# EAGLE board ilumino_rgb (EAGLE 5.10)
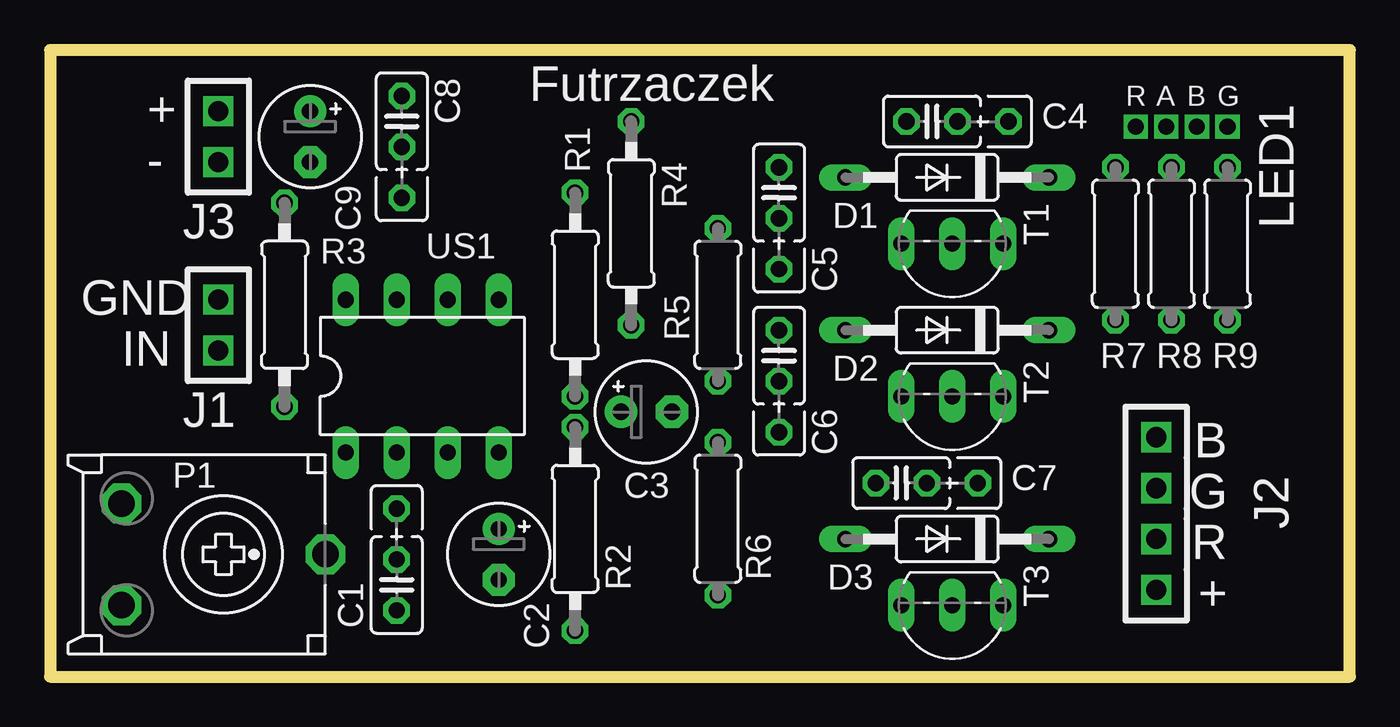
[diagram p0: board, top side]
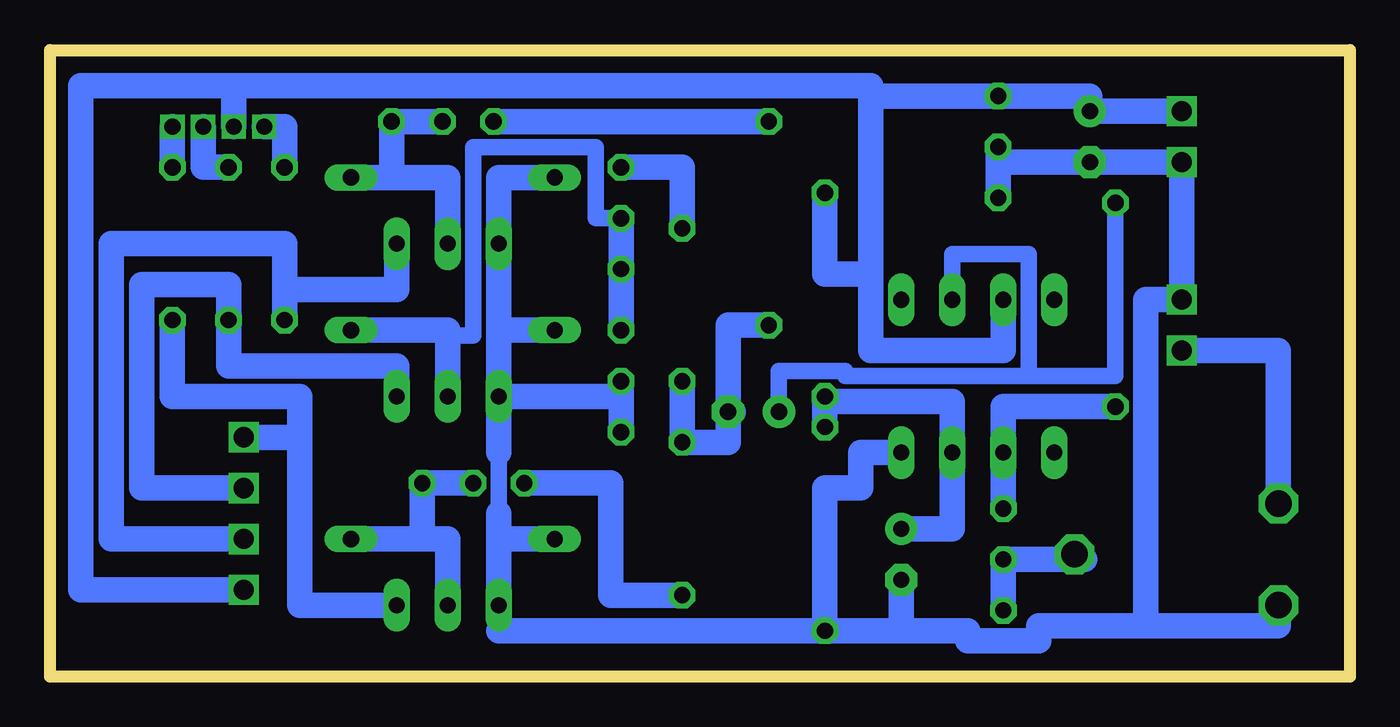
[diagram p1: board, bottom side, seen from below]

Size 64.77 x 31.24 mm. Coordinates in mm from the lower left corner, seen from the top.
Outline: 0,0 64.77,0 64.77,31.24 0,31.24 0,0
Copper layers (1*16): Top 0.035mm / dielectric 1.5mm / Bottom 0.035mm
Design rules "default": minimum track width 10mil, minimum drill 24mil, track to track 8mil, track to pad 8mil, pad to pad 8mil, via to via 8mil, smd to smd 8mil, copper to edge 40mil, drill to drill 8mil, minimum pad ring 10mil, minimum via ring 8mil, stop-mask expansion 4mil, vias tented up to drill 0mil, thermal gap 10mil

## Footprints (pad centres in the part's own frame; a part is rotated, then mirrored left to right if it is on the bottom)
C025_050-025X075 = drill 0.813 octagon: 1 -1.27,0; 2 1.27,0; 3 3.81,0
E2,5-5 = drill 0.813 pad 1.6 round: + -1.27,0 | drill 0.813 pad 1.6 octagon: - 1.27,0
C2992 = drill 0.813 long: A 5.08,0; C -5.08,0
ECP10S = drill 1.321 octagon: A -2.54,-5.08; E 2.54,-5.08; S 0,5.08
0207/10 = drill 0.813 octagon: 1 -5.08,0; 2 5.08,0
0207/7 = drill 0.813 octagon: 1 -3.81,0; 2 3.81,0
TO92- = drill 0.813 long: 1 2.54,0; 2 0,0; 3 -2.54,0
DIL08 = drill 0.813 long: 1 -3.81,-3.81; 2 -1.27,-3.81; 3 1.27,-3.81; 4 3.81,-3.81; 5 3.81,3.81; 6 1.27,3.81; 7 -1.27,3.81; 8 -3.81,3.81

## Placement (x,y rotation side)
C1  [C025_050-025X075]  17.27,4.57 90 top
C2  [E2,5-5]  22.35,6.1 270 top
C3  [E2,5-5]  29.72,13.21 0 top
C4  [C025_050-025X075]  43.94,27.69 0 top
C5  [C025_050-025X075]  36.32,24.13 270 top
C6  [C025_050-025X075]  36.32,16 270 top
C7  [C025_050-025X075]  42.42,9.65 0 top
C8  [C025_050-025X075]  17.53,27.69 270 top
C9  [E2,5-5]  12.95,26.92 270 top
D1  [C2992]  44.7,24.89 180 top
D2  [C2992]  44.7,17.27 180 top
D3  [C2992]  44.7,6.86 180 top
P1  [ECP10S]  8.64,6.1 270 top
R1  [0207/10]  26.16,19.05 270 top
R2  [0207/10]  26.16,7.37 270 top
R3  [0207/10]  11.68,18.54 90 top
R4  [0207/10]  28.96,22.61 270 top
R5  [0207/7]  33.27,18.54 270 top
R6  [0207/7]  33.27,7.87 270 top
R7  [0207/7]  53.09,21.59 270 top
R8  [0207/7]  55.88,21.59 270 top
R9  [0207/7]  58.67,21.59 270 top
T1  [TO92-]  44.96,21.59 180 top
T2  [TO92-]  44.96,13.97 180 top
T3  [TO92-]  44.96,3.56 180 top
US1  [DIL08]  18.54,14.99 0 top

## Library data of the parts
C1-C9 R1-R9 = rcl
D1-D3 = diode
P1 = pot
T1-T3 = transistor-npn
US1 = 40xx

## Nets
S$1: C2.+ R1.2 R2.1 US1.3
S$2: C8.1 C9.+ R1.1 US1.7
S$4: C3.+
S$5: R3.2
S$6: C1.3 R3.1
S$7: C1.1 C1.2 P1.S
S$8: C8.2 C8.3 C9.-
S$9: P1.A
S$12: C3.- R4.2 R5.2 R6.1
S$13: C6.2 C6.3
S$14: C4.2 T1.2
S$15: C7.1 R6.2
S$16: C5.2 C6.1 T2.2
S$18: C7.2 T3.2
S$19: R5.1
S$20: C2.- P1.E R2.2 US1.4
S$21: R9.2 T3.3
S$27: C4.1 R4.1
S$28: R8.1
S$29: R9.1
S$30: R7.1
S$31: T1.3
S$32: R8.2 T2.3

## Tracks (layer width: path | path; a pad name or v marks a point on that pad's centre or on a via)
S$1
  Bottom 1.27: R2.1 R1.2 26.16,13.72 19.81,13.72 19.81,11.43 US1.3 19.81,7.37 C2.+
S$2  (via drill 0.8, 1)
  Bottom 1.27: 8.64,28.19 C9.+ 12.95,28.96 C8.1 23.88,28.96 23.88,28.7 | US1.7 17.27,16.26 23.88,16.26 23.88,18.8 | 23.88,18.8 23.88,20.07 26.16,20.07 R1.1 | 23.88,28.7 23.88,18.8 | 23.88,28.7 23.88,29.46 52.83,29.46 | 52.83,29.46 55.63,29.46 v55.63,27.43 | 52.83,29.46 63.25,29.46 63.25,4.32 v55.12,4.32
S$3  (via drill 1)
  other vias: 55.12,6.86
S$4
  Bottom 0.813: 19.81,18.29 19.81,21.08 16,21.08 16,14.99 25.15,14.99 25.15,15.24 28.45,15.24 C3.+
S$5
  Bottom 0.813: 16.26,14.99 11.68,14.99 R3.2
S$6
  Bottom 1.27: 17.27,10.67 17.27,11.18 | 17.27,11.18 17.27,13.46 R3.1 | C1.3 17.27,11.18
S$7
  Bottom 1.27: C1.1 C1.2 13.21,5.84 P1.S
S$8  (via drill 1)
  Bottom 1.27: 10.16,2.79 10.16,18.8 v8.38,18.8 v8.38,25.65 C9.- 17.53,25.65 | 17.53,25.65 C8.2 | 17.53,25.65 C8.3
S$9  (via drill 1)
  Bottom 1.27: v8.38,16.26 3.56,16.26 P1.A
S$10  (via drill 1)
  other vias: 8.38,28.19
S$12
  Bottom 1.27: C3.- 30.73,13.21 | R4.2 30.99,17.53 C3.- | C3.- 30.99,11.68 R6.1 R5.2
S$13
  Bottom 0.813: 42.42,11.18 42.42,7.87
  Bottom 1.27: 39.37,24.89 42.42,24.89 42.42,22.1 | 42.42,22.1 42.42,21.34 | 42.42,13.97 42.42,11.18 | 42.42,13.97 42.42,22.1 | 42.42,13.97 36.32,13.97 36.32,14.48 | 36.32,14.48 C6.2 | C6.3 36.32,14.48 | 39.37,6.86 42.42,6.86 42.42,6.6 | 42.42,6.6 42.42,7.87 42.42,8.13 | 42.42,3.3 42.42,6.6
S$14
  Bottom 1.27: 49.53,24.89 47.75,24.89 | 47.75,24.89 44.96,24.89 T1.2 | C4.2 47.75,27.69 47.75,24.89
S$15
  Bottom 1.27: R6.2 36.83,4.06 36.83,9.65 C7.1
S$16
  Bottom 0.813: 44.96,17.02 43.69,17.02 43.69,26.42 37.59,26.42 37.59,22.86 C5.2
  Bottom 1.27: 49.53,17.27 44.96,17.27 44.96,17.02 T2.2 | C5.2 C6.1
S$17
  Bottom 1.27: 39.37,17.27 42.42,17.27 42.42,13.72
S$18
  Bottom 1.27: 49.53,6.86 46.23,6.86 | 46.23,6.86 44.96,6.86 T3.2 | C7.2 46.23,9.65 46.23,6.86
S$19
  Bottom 1.27: 36.32,25.4 33.27,25.4 R5.1
S$20
  Bottom 1.27: US1.4 24.38,11.18 24.38,9.4 26.16,9.4 26.16,7.37 26.16,5.33 R2.2 | R2.2 42.42,2.29 | 22.35,2.29 C2.- | 22.35,2.29 R2.2 | 22.35,2.29 19.05,2.29 19.05,1.78 15.49,1.78 15.49,2.54 3.56,2.54 P1.E
S$21
  Bottom 1.27: R9.2 58.67,13.97 52.32,13.97 52.32,3.56 T3.3
S$27
  Bottom 1.27: C4.1 R4.1
S$28  (via drill 0.8)
  Bottom 1.27: R8.1 57.15,25.4 v57.15,27.43
S$29  (via drill 0.8)
  Bottom 1.27: R9.1 v58.67,27.43
S$30  (via drill 0.8)
  Bottom 1.27: R7.1 53.09,27.43 v54.1,27.43
S$31  (via drill 1)
  Bottom 1.27: T1.3 47.5,19.3 53.09,19.3 53.09,19.05 | 53.09,19.05 53.09,17.78 | 53.09,19.05 53.09,21.59 61.72,21.59 61.72,6.86 v55.12,6.86
S$32  (via drill 1)
  Bottom 1.27: T2.3 47.5,15.49 55.88,15.49 R8.2 55.88,19.56 60.2,19.56 60.2,9.4 v55.12,9.4
S$34  (via drill 1)
  other vias: 55.12,9.4
S$36  (via drill 1)
  Bottom 1.27: v55.12,11.94 52.58,11.94

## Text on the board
tNames: Futrzaczek | R | A | B | G | + | - | LED1 | J3 | GND | IN | J1 | B | G | R | J2 | +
